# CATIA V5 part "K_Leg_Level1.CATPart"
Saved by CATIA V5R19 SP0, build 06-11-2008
Part number: Leg_Level1
Bounding box of the stored display mesh (mm): x -42.032 to 42.032, y 40.774 to 58.774, z -680 to 0
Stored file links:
  G:\Khaled_CFAO_2011\SIL\SIL_GR2\ctanaphiko\Khaled\CAD_ThinkMOTION\K_Leg_Level1.CATPart
  G:\Khaled_CFAO_2011\SIL\SIL_GR2\ctanaphiko\CATIA\Conception_Tripod.CATProduct
  G:\Khaled_CFAO_2011\SIL\SIL_GR2\ctanaphiko\CATIA\Squelette.CATPart
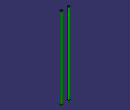
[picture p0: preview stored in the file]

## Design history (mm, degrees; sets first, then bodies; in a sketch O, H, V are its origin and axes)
External parameters (linked from other documents)
  External.Dia_Leg_Step1 = 18 mm
  External.Thick_Leg_Step1 = 1.8 mm
AxisSystem1: origin (0, 0, 0), X (1, 0, 0), Y (0, 1, 0), Z (0, 0, 1)
Set1
  Plane1 "Plan_Ref": linked copy from another document
  Point1: linked copy from another document
  Point2: linked copy from another document
  Line1: linked copy from another document
Body1 (main body)
  Sketch1 on Plane1, origin (0, 0, 0), H (1, 0, 0), V (0, 1, 0)
    circle A1 centre (-33.0316, 49.774) radius 9
    point P1 (-33.0316, 49.774)
    reference projected point E1 (-33.0316, 49.774) from Point1
    circle A2 centre (33.0316, 49.774) radius 9
    point P2 (33.0316, 49.774)
    reference projected point E2 (33.0316, 49.774) from Point2
    radius A1 = 9 {= External.Dia_Leg_Step1 /2}
    radius A2 = 9 {= External.Dia_Leg_Step1 /2}
    coincidence: P1 E1, P2 E2
  Rib1: profile Sketch1, centre curve Line1, thin wall 1.8 {= External.Thick_Leg_Step1}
